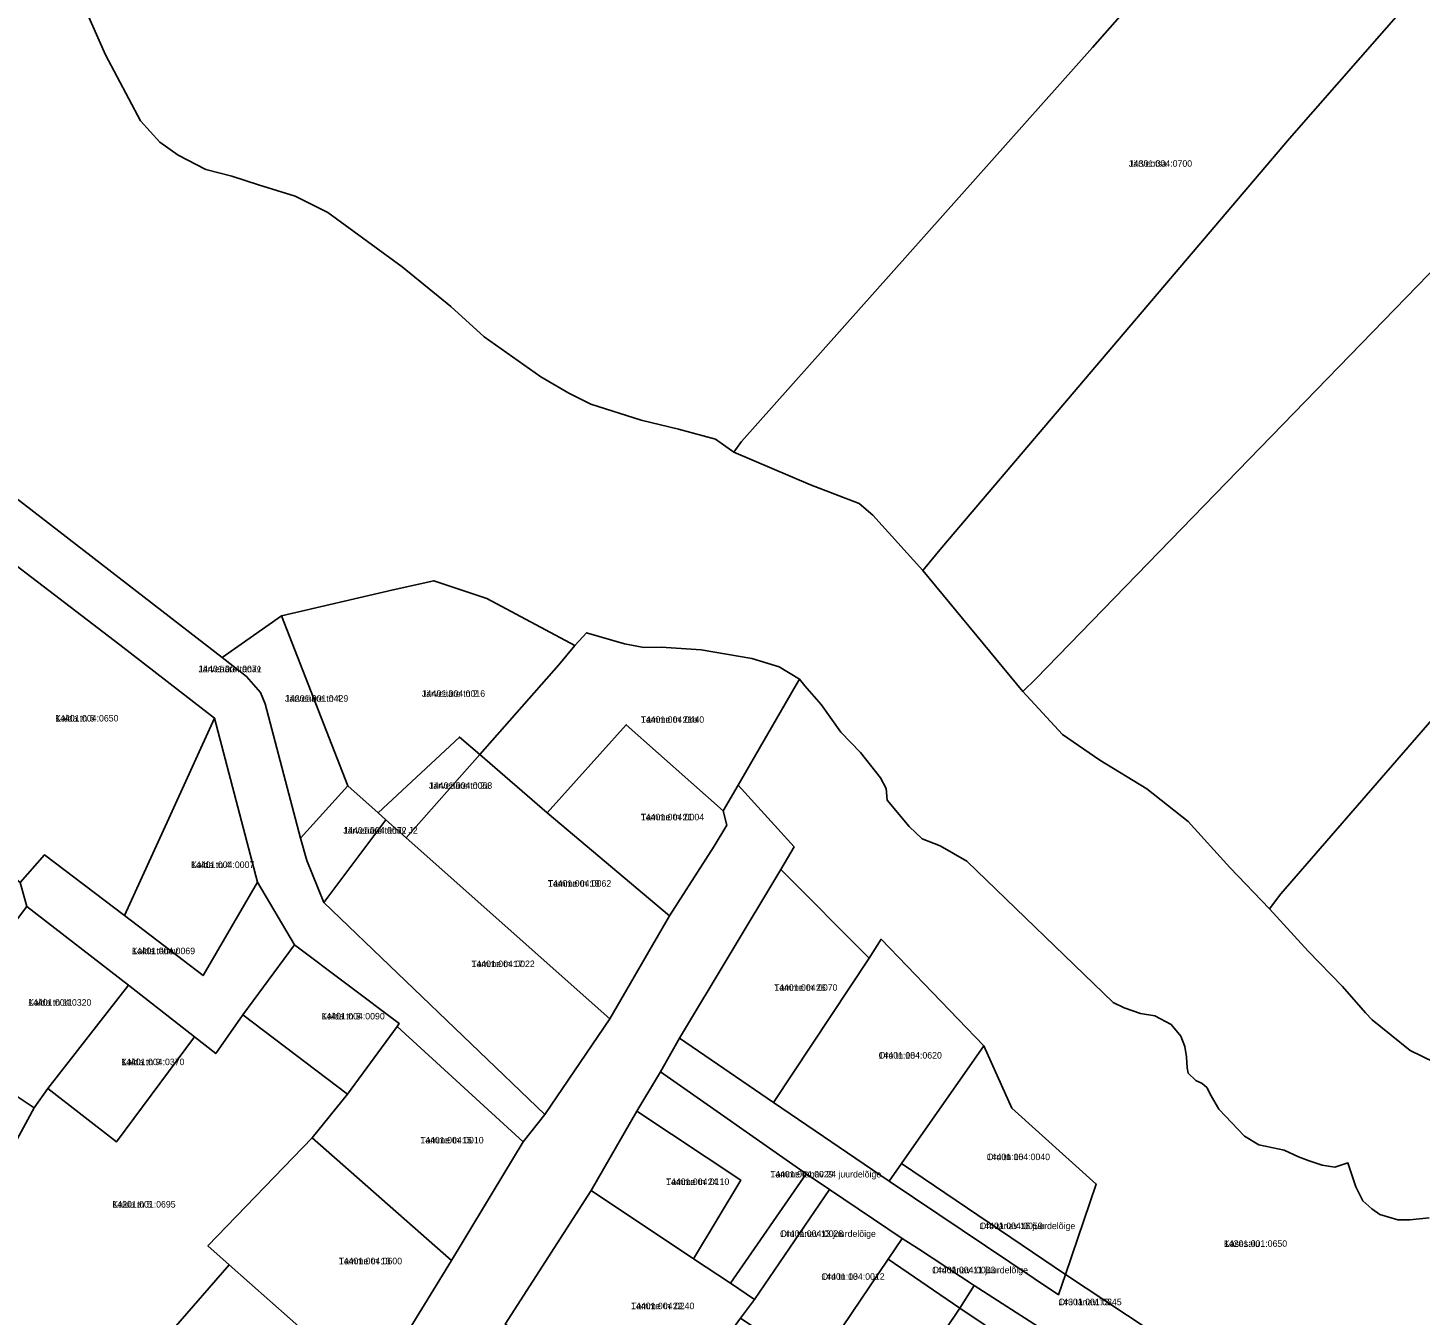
# Model space of a CAD drawing. Extents: x 640657 to 665127, y 6395726 to 6426831.
# Drawn here: x 650490.5 to 650809.6, y 6413110.9 to 6413405.9 of the extents above; entities that cross this region are included whole.
import ezdxf

# ---------------------------------------------------------------- set-up
doc = ezdxf.new("R2010")
doc.units = 0
for name, color, linetype in [('L_AADRESS', 7, 'Continuous'), ('PIIR', 7, 'Continuous'), ('TUNNUS', 7, 'Continuous')]:
    doc.layers.add(name, color=color, linetype=linetype)

msp = doc.modelspace()

# ---------------------------------------------------------------- linework, layer by layer
at = {"layer": 'PIIR'}
for points in [[(650960.7, 6413586.3), (651020.47, 6413562.79), (650934.78, 6413464.58), (650875.39, 6413396.42), (650865.22, 6413405.29), (650811.5, 6413349.45), (650721.48, 6413256.75), (650718.51, 6413253.84), (650695.62, 6413281.58), (650699.97, 6413286.8), (650779.67, 6413380.59), (650833.36, 6413441.9)], [(650699.97, 6413286.8), (650695.62, 6413281.58), (650684.17, 6413294.26), (650680.99, 6413296.89), (650669.9, 6413301.23), (650652.33, 6413308.72), (650654.02, 6413311.12), (650734.5, 6413401.45), (650742.42, 6413410.48), (650801.33, 6413477.77), (650833.36, 6413441.9), (650779.67, 6413380.59)], [(650775.04, 6413204.04), (650765.99, 6413213.47), (650756.47, 6413224.03), (650746.95, 6413231.53), (650736.17, 6413238.06), (650727.6, 6413243.95), (650718.51, 6413253.84), (650721.48, 6413256.75), (650811.5, 6413349.45), (650865.22, 6413405.29), (650875.39, 6413396.42), (650913.12, 6413363.57), (650777.7, 6413207.45)], [(650450.1, 6413320), (650455.02, 6413332.18), (650463.94, 6413326.65), (650483.68, 6413301.28), (650535.03, 6413261.62), (650540.6, 6413257.3), (650543.8, 6413253.6), (650544.9, 6413251), (650553, 6413220.2), (650554.4, 6413215.1), (650558.34, 6413205.48), (650608.99, 6413156.91), (650603.97, 6413150.57), (650575.14, 6413177.06), (650575.61, 6413177.72), (650551.59, 6413195.75), (650543.11, 6413210.13), (650533.28, 6413247.75), (650511.53, 6413264.56), (650476.36, 6413291.39), (650458.4, 6413315.2)], [(650511.53, 6413264.56), (650533.28, 6413247.75), (650522.77, 6413224.71), (650512.65, 6413202.51), (650494.29, 6413216.4), (650488.73, 6413210.04), (650459.61, 6413234.81), (650457.03, 6413237.01), (650463.49, 6413255.18), (650469.35, 6413271.66), (650476.36, 6413291.39)], [(650570.74, 6413226.01), (650563.79, 6413232.22), (650548.6, 6413271.2), (650574.2, 6413277.14), (650583.5, 6413279.2), (650595.65, 6413275.14), (650615.86, 6413264.36), (650612.17, 6413259.96), (650594.07, 6413239.37), (650589.4, 6413243.4)], [(650553, 6413220.2), (650544.9, 6413251), (650543.8, 6413253.6), (650540.6, 6413257.3), (650535.03, 6413261.62), (650548.6, 6413271.2), (650563.79, 6413232.22)], [(650609.53, 6413226.02), (650594.07, 6413239.37), (650612.17, 6413259.96), (650615.86, 6413264.36), (650617.69, 6413266.39), (650618.49, 6413267.28), (650627.26, 6413264.79), (650631.68, 6413263.88), (650635.63, 6413263.98), (650644.78, 6413263.35), (650656.43, 6413261.4), (650662.7, 6413259.49), (650667.31, 6413256.69), (650666.02, 6413254.46), (650653.27, 6413232.35), (650649.88, 6413226.49), (650627.65, 6413246.22)], [(650530.63, 6413188.72), (650512.65, 6413202.51), (650522.77, 6413224.71), (650533.28, 6413247.75), (650543.11, 6413210.13)], [(650647.75, 6413218.37), (650637.53, 6413202.38), (650609.53, 6413226.02), (650627.65, 6413246.22), (650649.88, 6413226.49), (650650.66, 6413223.2)], [(650570.74, 6413226.01), (650589.4, 6413243.4), (650594.07, 6413239.37), (650577.19, 6413220.28), (650572.55, 6413224.41)], [(650577.19, 6413220.28), (650594.07, 6413239.37), (650609.53, 6413226.02), (650637.53, 6413202.38), (650623.88, 6413178.8)], [(650553, 6413220.2), (650563.79, 6413232.22), (650570.74, 6413226.01), (650572.55, 6413224.41), (650558.34, 6413205.48), (650554.4, 6413215.1)], [(650623.88, 6413178.8), (650608.99, 6413156.91), (650558.34, 6413205.48), (650572.55, 6413224.41), (650577.19, 6413220.28)], [(650488.73, 6413210.04), (650494.29, 6413216.4), (650512.65, 6413202.51), (650530.63, 6413188.72), (650543.11, 6413210.13), (650551.59, 6413195.75), (650539.77, 6413179.73), (650533.54, 6413170.85), (650528.7, 6413174.65), (650513.56, 6413186.52), (650490.25, 6413204.53)], [(650639.81, 6413174.35), (650663.04, 6413213.01), (650683.29, 6413192.67), (650661.38, 6413159.66)], [(650467.52, 6413174.58), (650469.82, 6413177.56), (650490.25, 6413204.53), (650513.56, 6413186.52), (650495.03, 6413162.84), (650491.92, 6413158.4)], [(650661.38, 6413159.66), (650683.29, 6413192.67), (650686.03, 6413197.06), (650709.58, 6413172.62), (650690.72, 6413145.64), (650687.87, 6413141.56)], [(650551.59, 6413195.75), (650575.61, 6413177.72), (650575.14, 6413177.06), (650563.74, 6413161.57), (650539.77, 6413179.73)], [(650495.03, 6413162.84), (650513.56, 6413186.52), (650528.7, 6413174.65), (650510.82, 6413150.61)], [(650533.54, 6413170.85), (650539.77, 6413179.73), (650563.74, 6413161.57), (650555.61, 6413151.56), (650531.75, 6413126.74), (650536.61, 6413122.42), (650509.55, 6413091.33), (650495.52, 6413102.83), (650471.6, 6413121.03), (650491.92, 6413158.4), (650495.03, 6413162.84), (650510.82, 6413150.61), (650528.7, 6413174.65)], [(650466.21, 6413175.44), (650467.52, 6413174.58), (650491.92, 6413158.4), (650471.6, 6413121.03), (650468.8, 6413123.7), (650444.55, 6413146.98)], [(650563.74, 6413161.57), (650575.14, 6413177.06), (650603.97, 6413150.57), (650587.57, 6413123.41), (650555.61, 6413151.56)], [(650639.81, 6413174.35), (650661.38, 6413159.66), (650687.87, 6413141.56), (650726.69, 6413115.56), (650728.32, 6413120.2), (650817.6, 6413061.15), (650809.09, 6413051.96), (650774.49, 6413073.67), (650757.49, 6413085.02), (650736.91, 6413098.43), (650728.56, 6413104.06), (650707.39, 6413117.67), (650694.6, 6413126.1), (650690.86, 6413128.47), (650674.2, 6413139.68), (650668.91, 6413143.29), (650635.45, 6413166.68)], [(650709.58, 6413172.62), (650716.05, 6413158.35), (650735.38, 6413140.92), (650728.32, 6413120.2), (650690.72, 6413145.64)], [(650635.45, 6413166.68), (650668.91, 6413143.29), (650651.55, 6413118.19), (650643.06, 6413123.78), (650653.88, 6413141.85), (650630.05, 6413157.65)], [(650643.06, 6413123.78), (650619.58, 6413139.45), (650630.05, 6413157.65), (650653.88, 6413141.85)], [(650536.61, 6413122.42), (650531.75, 6413126.74), (650555.61, 6413151.56), (650587.57, 6413123.41), (650569.27, 6413093.53)], [(650668.91, 6413143.29), (650674.2, 6413139.68), (650657.04, 6413114.5), (650651.55, 6413118.19)], [(650690.72, 6413145.64), (650728.32, 6413120.2), (650726.69, 6413115.56), (650687.87, 6413141.56)], [(650674.2, 6413139.68), (650690.86, 6413128.47), (650687.66, 6413123.7), (650670.89, 6413098.82), (650653.85, 6413110.19), (650657.04, 6413114.5)], [(650619.58, 6413139.45), (650643.06, 6413123.78), (650651.55, 6413118.19), (650657.04, 6413114.5), (650653.85, 6413110.19), (650635.67, 6413085.06), (650599.89, 6413108.8)], [(650690.86, 6413128.47), (650694.6, 6413126.1), (650707.39, 6413117.67), (650704.06, 6413112.49), (650687.66, 6413123.7)], [(650670.89, 6413098.82), (650687.66, 6413123.7), (650704.06, 6413112.49), (650687.4, 6413087.54)], [(650509.55, 6413091.33), (650536.61, 6413122.42), (650569.27, 6413093.53), (650548.62, 6413059.33), (650545.59, 6413061.79)], [(650707.39, 6413117.67), (650728.56, 6413104.06), (650708.25, 6413074.02), (650704.19, 6413076.67), (650720.8, 6413101.26), (650704.06, 6413112.49)], [(650687.4, 6413087.54), (650704.06, 6413112.49), (650720.8, 6413101.26), (650704.19, 6413076.67)]]:
    msp.add_lwpolyline(points, close=True, dxfattribs=at)
for points in [[(650742.42, 6413410.48), (650734.5, 6413401.45), (650654.02, 6413311.12), (650652.33, 6413308.72), (650648.11, 6413311.68), (650639.6, 6413313.94), (650631.08, 6413316), (650619.55, 6413319.66), (650614.49, 6413322.22), (650608.05, 6413325.93), (650595.07, 6413335.16), (650587.39, 6413342.09), (650576.28, 6413351.15), (650559.24, 6413363.65), (650551.78, 6413367.35), (650543.35, 6413370), (650537.25, 6413371.92), (650531.26, 6413373.48), (650524.96, 6413376.74), (650520.72, 6413379.74), (650516.26, 6413384.61), (650508.25, 6413399.76), (650501.51, 6413415.07)], [(650501.51, 6413415.07), (650508.25, 6413399.76), (650516.26, 6413384.61), (650520.72, 6413379.74), (650524.96, 6413376.74), (650531.26, 6413373.48), (650537.25, 6413371.92), (650543.35, 6413370), (650551.78, 6413367.35), (650559.24, 6413363.65), (650576.28, 6413351.15), (650587.39, 6413342.09), (650595.07, 6413335.16), (650608.05, 6413325.93), (650614.49, 6413322.22), (650619.55, 6413319.66), (650631.08, 6413316), (650639.6, 6413313.94), (650648.11, 6413311.68), (650652.33, 6413308.72), (650669.9, 6413301.23), (650680.99, 6413296.89), (650684.17, 6413294.26), (650695.62, 6413281.58), (650718.51, 6413253.84), (650727.6, 6413243.95), (650736.17, 6413238.06), (650746.95, 6413231.53), (650756.47, 6413224.03), (650765.99, 6413213.47), (650775.04, 6413204.04), (650783.94, 6413194.3), (650791.83, 6413186.2), (650797.1, 6413180.18), (650798.61, 6413178.54), (650807.32, 6413171.55), (650812.82, 6413168.84)], [(650812.82, 6413168.84), (650807.32, 6413171.55), (650798.61, 6413178.54), (650797.1, 6413180.18), (650791.83, 6413186.2), (650783.94, 6413194.3), (650775.04, 6413204.04), (650777.7, 6413207.45), (650913.12, 6413363.57)], [(650811.64, 6413133.22), (650807.27, 6413132.7), (650804.49, 6413132.71), (650800.39, 6413133.92), (650798.54, 6413135.25), (650796.44, 6413137.11), (650794.86, 6413140.29), (650793.05, 6413145.77), (650790.04, 6413144.8), (650787.17, 6413145.23), (650784.2, 6413146.27), (650781.75, 6413147.2), (650778.46, 6413148.66), (650772.63, 6413149.89), (650769.37, 6413151.89), (650763.44, 6413158.13), (650761.73, 6413161.18), (650760.68, 6413163.03), (650759.62, 6413163.96), (650758.17, 6413164.63), (650756.46, 6413166.36), (650756.2, 6413167.55), (650756.07, 6413170.06), (650755.68, 6413172.44), (650754.77, 6413174.83), (650752.53, 6413177.48), (650748.83, 6413179.48), (650745.52, 6413180.02), (650741.77, 6413181.36), (650739.24, 6413182.53), (650705.71, 6413214.97), (650699.6, 6413218.42), (650695.43, 6413220.07), (650692.5, 6413222.86), (650687.45, 6413228.92), (650687.24, 6413231.63), (650685.91, 6413234.02), (650681.33, 6413239.87), (650676.79, 6413244.51), (650672.31, 6413250.83), (650668.6, 6413255.15), (650667.36, 6413256.66), (650667.31, 6413256.69), (650662.7, 6413259.49), (650656.43, 6413261.4), (650644.78, 6413263.35), (650635.63, 6413263.98), (650631.68, 6413263.88), (650627.26, 6413264.79), (650618.49, 6413267.28), (650617.69, 6413266.39), (650615.86, 6413264.36), (650595.65, 6413275.14), (650583.5, 6413279.2), (650574.2, 6413277.14), (650548.6, 6413271.2), (650535.03, 6413261.62), (650483.68, 6413301.28)], [(650817.6, 6413061.15), (650728.32, 6413120.2), (650735.38, 6413140.92), (650716.05, 6413158.35), (650709.58, 6413172.62), (650686.03, 6413197.06), (650683.29, 6413192.67), (650663.04, 6413213.01), (650666.12, 6413218.2), (650653.27, 6413232.35), (650666.02, 6413254.46), (650667.31, 6413256.69), (650667.36, 6413256.66), (650668.6, 6413255.15), (650672.31, 6413250.83), (650676.79, 6413244.51), (650681.33, 6413239.87), (650685.91, 6413234.02), (650687.24, 6413231.63), (650687.45, 6413228.92), (650692.5, 6413222.86), (650695.43, 6413220.07), (650699.6, 6413218.42), (650705.71, 6413214.97), (650739.24, 6413182.53), (650741.77, 6413181.36), (650745.52, 6413180.02), (650748.83, 6413179.48), (650752.53, 6413177.48), (650754.77, 6413174.83), (650755.68, 6413172.44), (650756.07, 6413170.06), (650756.2, 6413167.55), (650756.46, 6413166.36), (650758.17, 6413164.63), (650759.62, 6413163.96), (650760.68, 6413163.03), (650761.73, 6413161.18), (650763.44, 6413158.13), (650769.37, 6413151.89), (650772.63, 6413149.89), (650778.46, 6413148.66), (650781.75, 6413147.2), (650784.2, 6413146.27), (650787.17, 6413145.23), (650790.04, 6413144.8), (650793.05, 6413145.77), (650794.86, 6413140.29), (650796.44, 6413137.11), (650798.54, 6413135.25), (650800.39, 6413133.92), (650804.49, 6413132.71), (650807.27, 6413132.7), (650811.64, 6413133.22)], [(650569.27, 6413093.53), (650587.57, 6413123.41), (650603.97, 6413150.57), (650608.99, 6413156.91), (650623.88, 6413178.8), (650637.53, 6413202.38), (650647.75, 6413218.37), (650650.66, 6413223.2), (650649.88, 6413226.49), (650653.27, 6413232.35), (650666.12, 6413218.2), (650663.04, 6413213.01), (650639.81, 6413174.35), (650635.45, 6413166.68), (650630.05, 6413157.65), (650619.58, 6413139.45), (650599.89, 6413108.8)]]:
    msp.add_lwpolyline(points, dxfattribs=at)

# ---------------------------------------------------------------- texts
at = {"layer": 'L_AADRESS'}
for s, p in [('Järveotsa', (650742.84, 6413374.11)), ('Järveääre tänav', (650529.55, 6413258.25)), ('Järveääre tn 4', (650549.41, 6413251.49)), ('Järveääre tn 2', (650580.78, 6413252.61)), ('Kalda tn 6', (650496.74, 6413246.95)), ('Tamme tn 21b', (650630.99, 6413246.65)), ('Järveääre tn 2a', (650582.41, 6413231.53)), ('Tamme tn 21', (650630.98, 6413224.3)), ('Järveääre tänav J2', (650562.77, 6413221.24)), ('Kalda tn 4', (650527.88, 6413213.37)), ('Tamme tn 19', (650609.69, 6413209.09)), ('Kalda tänav', (650514.3, 6413193.62)), ('Tamme tn 17', (650592.16, 6413190.66)), ('Tamme tn 26', (650661.55, 6413185.22)), ('Kalda tn 11', (650490.54, 6413181.81)), ('Kalda tn 3', (650557.77, 6413178.66)), ('Kalda tn 9', (650511.87, 6413168.18)), ('Oru tn 18', (650685.48, 6413169.69)), ('Tamme tn 15', (650580.44, 6413150.24)), ('Oru tn 16', (650710.27, 6413146.41)), ('Tamme tänav 24 juurdelõige', (650660.66, 6413142.44)), ('Tamme tn 24', (650636.75, 6413140.71)), ('Kalda tn 5', (650509.84, 6413135.53)), ('Oru tänav 13 juurdelõige', (650662.88, 6413128.81)), ('Oru tänav 16 juurdelõige', (650708.59, 6413130.6)), ('Kasesalu', (650764.62, 6413126.54)), ('Tamme tn 13', (650561.75, 6413122.54)), ('Oru tn 13', (650672.36, 6413118.98)), ('Oru tänav 11 juurdelõige', (650697.75, 6413120.48)), ('Oru tänav T3', (650726.69, 6413113.16)), ('Tamme tn 22', (650628.74, 6413112.25))]:
    msp.add_text(s, height=1.5, dxfattribs=at).set_placement(p)
at = {"layer": 'TUNNUS'}
for s, p in [('14301:004:0700', (650742.84, 6413374.11)), ('14401:004:0071', (650529.55, 6413258.25)), ('14201:001:0429', (650549.41, 6413251.49)), ('14401:004:0016', (650580.78, 6413252.61)), ('14401:004:0650', (650496.74, 6413246.95)), ('14401:004:0440', (650630.99, 6413246.65)), ('14401:004:0063', (650582.41, 6413231.53)), ('14401:004:0004', (650630.98, 6413224.3)), ('14401:004:0072', (650562.77, 6413221.24)), ('14401:004:0007', (650527.88, 6413213.37)), ('14401:004:0062', (650609.69, 6413209.09)), ('14401:004:0069', (650514.3, 6413193.62)), ('14401:004:0022', (650592.16, 6413190.66)), ('14401:004:0070', (650661.55, 6413185.22)), ('14401:004:0320', (650490.54, 6413181.81)), ('14401:004:0090', (650557.77, 6413178.66)), ('14401:004:0370', (650511.87, 6413168.18)), ('14401:004:0620', (650685.48, 6413169.69)), ('14401:004:0010', (650580.44, 6413150.24)), ('14401:004:0040', (650710.27, 6413146.41)), ('14401:004:0029', (650660.66, 6413142.44)), ('14401:004:0110', (650636.75, 6413140.71)), ('14201:001:0695', (650509.84, 6413135.53)), ('14401:004:0028', (650662.88, 6413128.81)), ('14401:004:0059', (650708.59, 6413130.6)), ('14201:001:0650', (650764.62, 6413126.54)), ('14401:004:0600', (650561.75, 6413122.54)), ('14401:004:0012', (650672.36, 6413118.98)), ('14401:004:0033', (650697.75, 6413120.48)), ('14301:001:0345', (650726.69, 6413113.16)), ('14401:004:0240', (650628.74, 6413112.25))]:
    msp.add_text(s, height=1.5, dxfattribs=at).set_placement(p)

doc.saveas('drawing.dxf')
